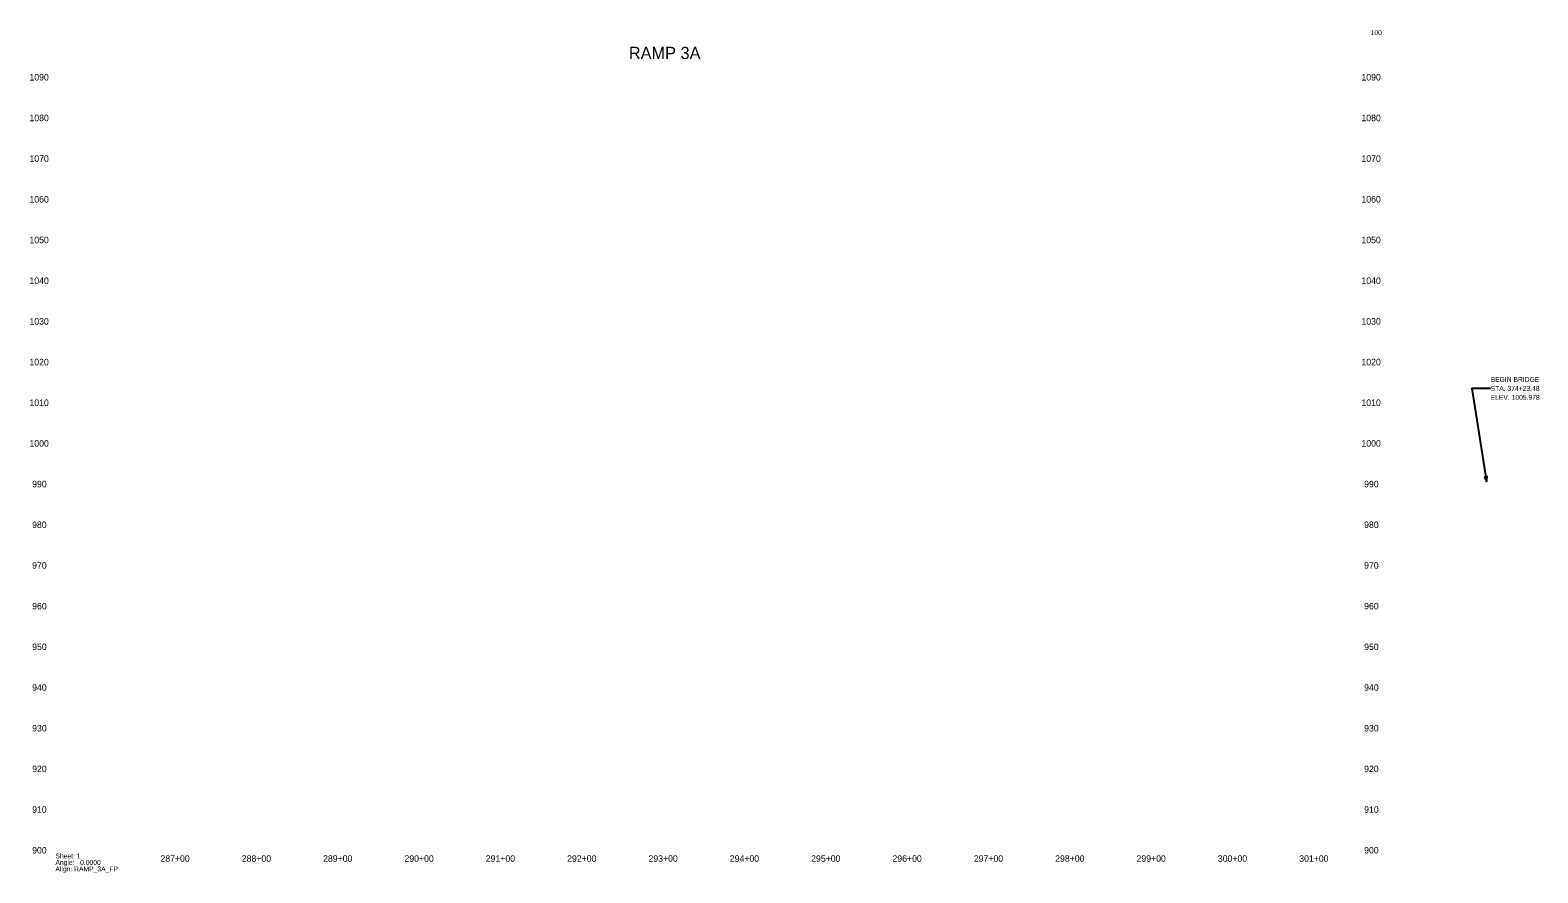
# Model space of a CAD drawing. Extents: x 16972898 to 16974751, y 12561645 to 12562681.
import ezdxf

# ---------------------------------------------------------------- set-up
doc = ezdxf.new("R2010")
doc.units = 0
for name, color, linetype in [('Default', 7, 'Continuous'), ('RD_DDB_ElevTX', 7, 'Continuous'), ('RD_DDB_StaTX', 7, 'Continuous'), ('RD_SHT_TX', 7, 'Continuous')]:
    doc.layers.add(name, color=color, linetype=linetype)

msp = doc.modelspace()

# ---------------------------------------------------------------- linework, layer by layer
at = {"layer": 'RD_SHT_TX'}
msp.add_lwpolyline([(16974693.1, 12562240.5), (16974670.2, 12562240.5), (16974688, 12562126.2)], dxfattribs=at)
msp.add_lwpolyline([(16974685.6, 12562131.7), (16974688, 12562126.2), (16974688.7, 12562132.2)], close=True, dxfattribs=at)

# ---------------------------------------------------------------- texts
at = {"layer": 'Default'}
for s, p in [('Sheet: 1', (16972928.7, 12561662.9)), ('Angle:   0.0000', (16972928.7, 12561654.9)), ('Align: RAMP_3A_FP', (16972928.7, 12561646.9))]:
    msp.add_text(s, height=6, dxfattribs=at).set_placement(p)
at = {"layer": 'RD_DDB_ElevTX'}
for s, p in [('1090', (16972896.8, 12562618.9)), ('1090', (16974534.3, 12562618.9)), ('1080', (16972896.8, 12562568.9)), ('1080', (16974534.3, 12562568.9)), ('1070', (16972896.8, 12562518.9)), ('1070', (16974534.3, 12562518.9)), ('1060', (16972896.8, 12562468.9)), ('1060', (16974534.3, 12562468.9)), ('1050', (16972896.8, 12562418.9)), ('1050', (16974534.3, 12562418.9)), ('1040', (16972896.8, 12562368.9)), ('1040', (16974534.3, 12562368.9)), ('1030', (16972896.8, 12562318.9)), ('1030', (16974534.3, 12562318.9)), ('1020', (16972896.8, 12562268.9)), ('1020', (16974534.3, 12562268.9)), ('1010', (16972896.8, 12562218.9)), ('1010', (16974534.3, 12562218.9)), ('1000', (16972896.8, 12562168.9)), ('1000', (16974534.3, 12562168.9)), ('990', (16972900.1, 12562118.9)), ('990', (16974537.6, 12562118.9)), ('980', (16972900.1, 12562068.9)), ('980', (16974537.6, 12562068.9)), ('970', (16972900.1, 12562018.9)), ('970', (16974537.6, 12562018.9)), ('960', (16972900.1, 12561968.9)), ('960', (16974537.6, 12561968.9)), ('950', (16972900.1, 12561918.9)), ('950', (16974537.6, 12561918.9)), ('940', (16972900.1, 12561868.9)), ('940', (16974537.6, 12561868.9)), ('930', (16972900.1, 12561818.9)), ('930', (16974537.6, 12561818.9)), ('920', (16972900.1, 12561768.9)), ('920', (16974537.6, 12561768.9)), ('910', (16972900.1, 12561718.9)), ('910', (16974537.6, 12561718.9)), ('900', (16972900.1, 12561668.9)), ('900', (16974537.6, 12561668.9))]:
    msp.add_text(s, height=8, dxfattribs=at).set_placement(p)
at = {"layer": 'RD_DDB_StaTX'}
for s, p in [('287+00', (16973057.8, 12561658.7)), ('288+00', (16973157.8, 12561658.7)), ('289+00', (16973257.8, 12561658.7)), ('290+00', (16973357.8, 12561658.7)), ('291+00', (16973457.8, 12561658.7)), ('292+00', (16973557.8, 12561658.7)), ('293+00', (16973657.8, 12561658.7)), ('294+00', (16973757.8, 12561658.7)), ('295+00', (16973857.8, 12561658.7)), ('296+00', (16973957.8, 12561658.7)), ('297+00', (16974057.8, 12561658.7)), ('298+00', (16974157.8, 12561658.7)), ('299+00', (16974257.8, 12561658.7)), ('300+00', (16974357.8, 12561658.7)), ('301+00', (16974457.8, 12561658.7))]:
    msp.add_text(s, height=8, dxfattribs=at).set_placement(p)
at = {"layer": 'RD_SHT_TX'}
for s, height, p in [('100', 6, (16974545.6, 12562674.7)), ('RAMP 3A', 15, (16973633.7, 12562645.3))]:
    msp.add_text(s, height=height, dxfattribs=at).set_placement(p)
for s, p in [('STA. 374+23.48', (16974693.1, 12562237.5)), ('BEGIN BRIDGE', (16974693.1, 12562248.5)), ('ELEV. 1005.978', (16974693.1, 12562226.5))]:
    msp.add_text(s, height=6, rotation=360, dxfattribs=at).set_placement(p)

doc.saveas('drawing.dxf')
